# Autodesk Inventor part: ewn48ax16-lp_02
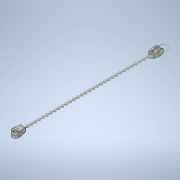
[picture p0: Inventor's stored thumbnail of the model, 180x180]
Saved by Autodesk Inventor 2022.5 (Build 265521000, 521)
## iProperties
Created: 2021-08
Part Number: ewn48ax16-lp_02
Material: 一般
Document SubType Name: Modeling
Designer: ImaoCorp
Density: 1 g/cm^3
Appearance: 既定
Author: ImaoCorp
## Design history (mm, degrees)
feature "ewn48ax16-lp_02"
node "ソリッド1"
